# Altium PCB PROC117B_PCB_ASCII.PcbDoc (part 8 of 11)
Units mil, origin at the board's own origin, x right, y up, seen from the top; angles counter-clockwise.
Board outline 2480.32 x 3185.25 mil, 8 copper layers (Top Layer, L2_GND1, L3_SIG1, L4_PWR1, L5_PWR2, L6_SIG2, L7_GND2, Bottom Layer), stack 57.4 mil thick; 456 components, 292 nets, 7831 pads, 2905 vias.
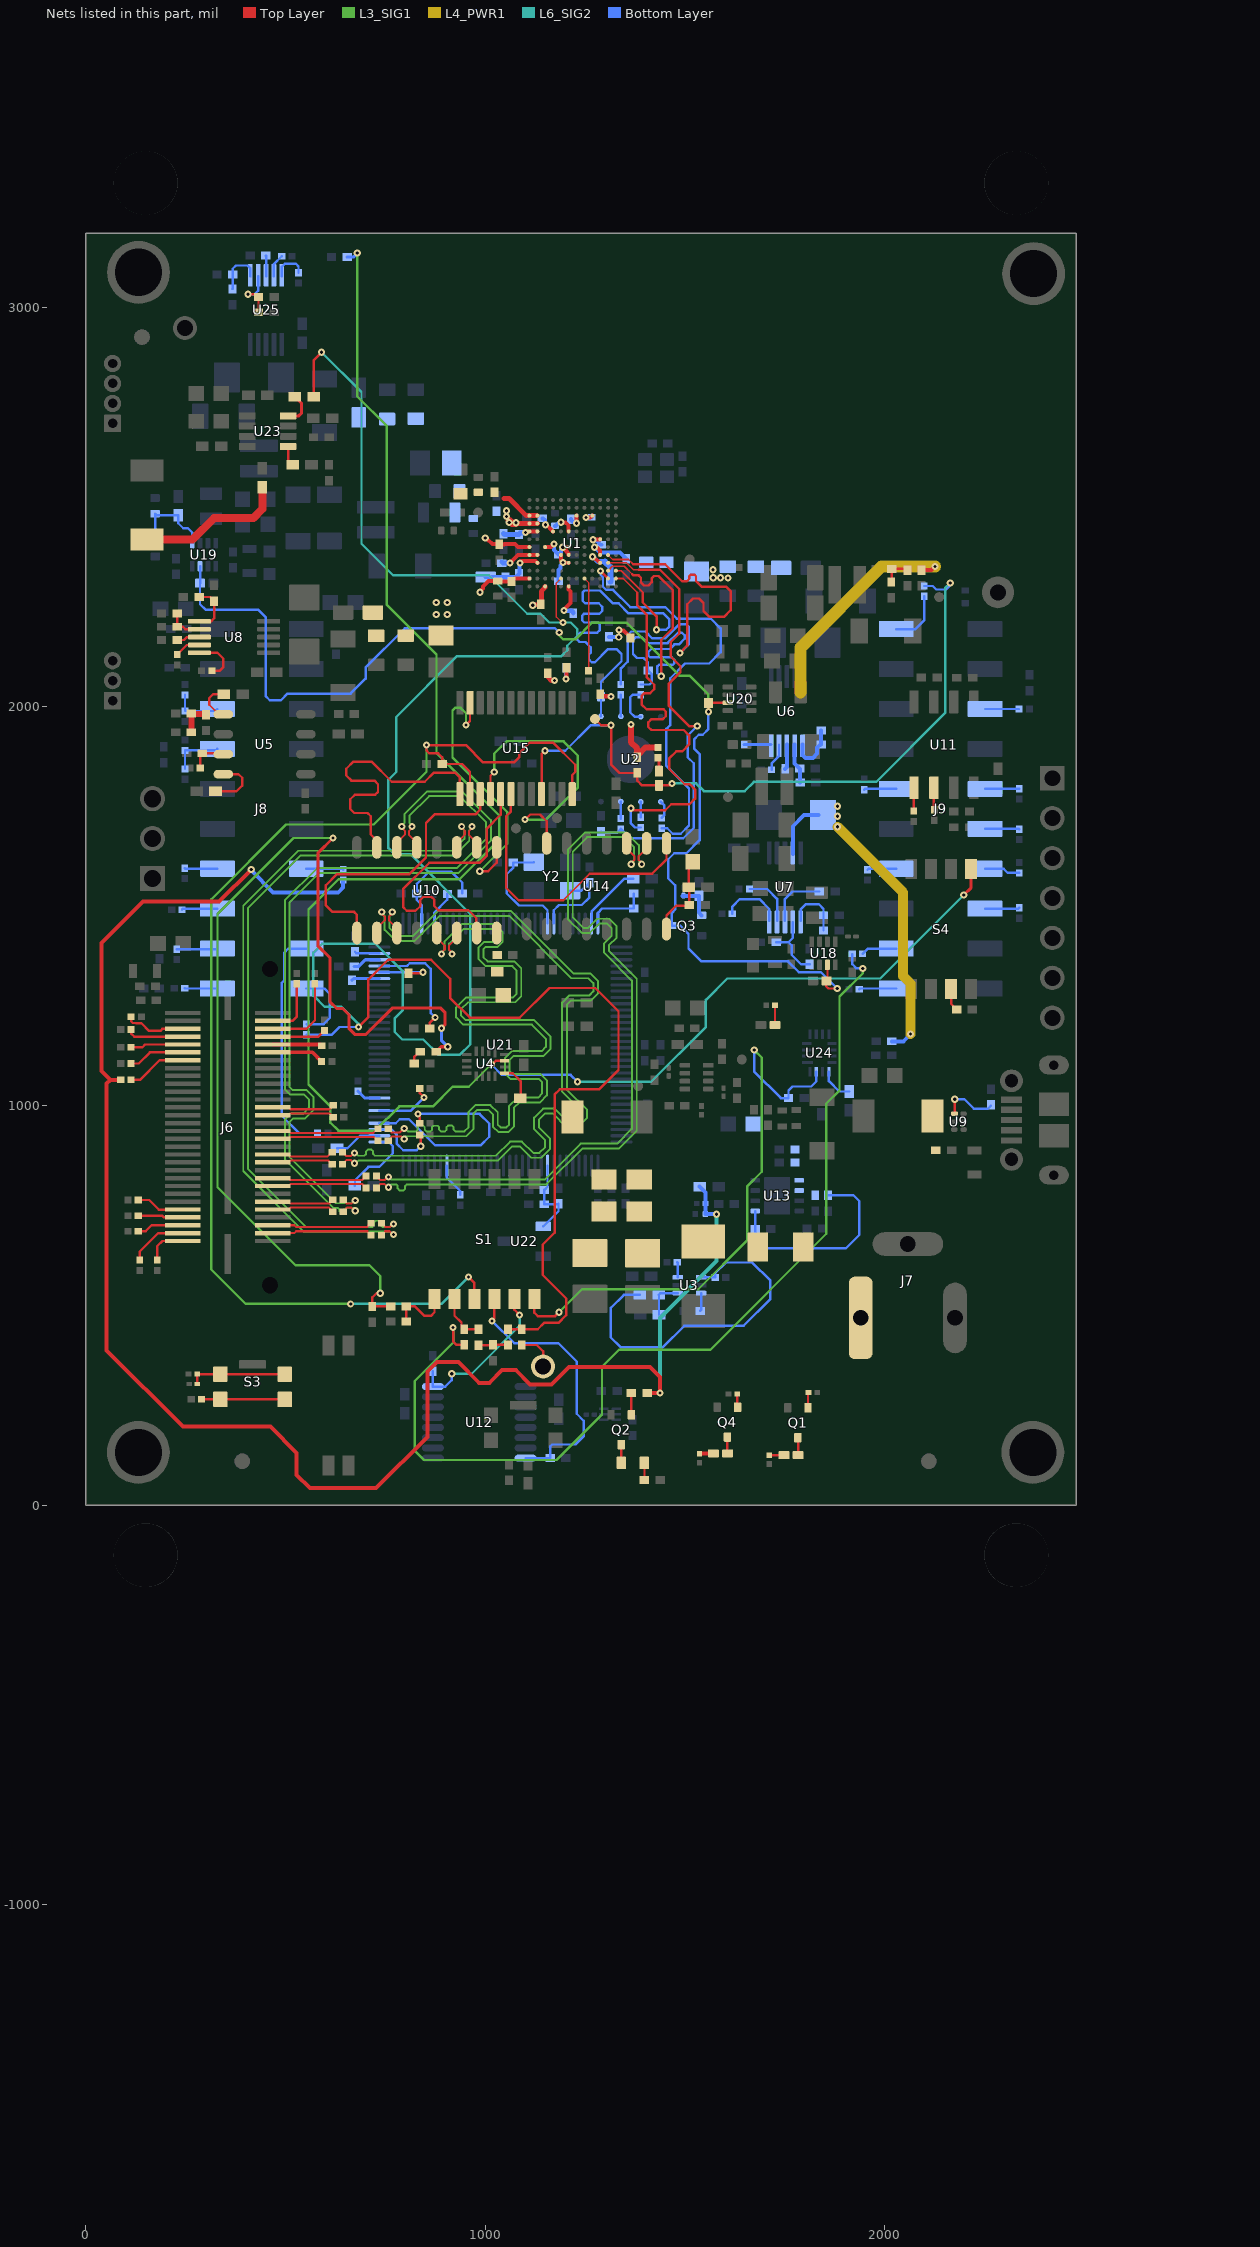
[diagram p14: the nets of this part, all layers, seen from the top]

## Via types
v1: diameter 18, hole 8, Top Layer to Bottom Layer, tented both sides, 2905 vias

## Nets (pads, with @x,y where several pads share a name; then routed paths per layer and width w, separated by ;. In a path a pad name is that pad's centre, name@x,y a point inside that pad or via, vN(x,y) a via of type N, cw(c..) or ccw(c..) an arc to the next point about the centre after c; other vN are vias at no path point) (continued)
MCU_SOP1: R16.1 R155.1 | length 2518.2
  Top Layer w6: v1(919.91,444.7) 919.89,409.86 928.62,401.13 R16.1@947.67,401.13
  L3_SIG1 w6: v1(919.91,444.7) 919.91,406.78 823.3,310.16 823.3,136.89 847.14,113.05 1178.59,113.05 1292.69,227.15 1292.69,346.62 1335.23,389.16 1564.11,389.16 1854.35,679.4 1854.35,1005.5 1887.46,1038.62 1887.46,1273.32 1945.7,1331.56 1945.7,1343.79 v1(1945.49,1344)
  Bottom Layer w6: R155.1@1919.28,1380.28 1919.28,1354.91 1930.18,1344 v1(1945.49,1344)
MODE: Q3.3 R232.2 R238.2 R244.2 U18.3 U19.3 U20.3 | length 3105.4
  Top Layer w6: v1(1559.26,1986.68) 1559.26,2008.42 R244.2@1559.69,2008.85 1607.59,2008.85 U20.3@1608.17,2009.43 ; U18.3@1857.32,1352.93 1857.32,1315.52 R232.2@1854.91,1313.11 1854.46,1312.66 1854.46,1299.03 1859.63,1293.86 v1(1881.7,1293.86)
  L3_SIG1 w6: v1@1185.61,2185.88 1185.61,2177.85 1195.54,2167.91 1226,2167.91 1267.97,2209.88 1353.82,2209.88 1486.51,2077.19 1511.97,2077.19 1559.26,2029.9 v1(1559.26,1986.68)
  Bottom Layer w6: U19.3@286.16,2351.04 R238.2@286.11,2308.62 R238.2@286.11,2308.62 286.11,2256.1 299.66,2242.55 431.64,2242.55 450.31,2223.88 450.31,2025.87 460.62,2015.55 488.66,2015.55 505.32,2032.22 663.1,2032.22 700.58,2069.7 700.58,2097.5 798.99,2195.91 1175.04,2195.91 v1(1185.61,2185.34) ; v1(1559.26,1986.68) 1559.26,1943.26 1545.11,1929.1 1535.12,1929.1 1523.26,1917.24 1523.26,1894.67 1537.18,1880.74 1537.18,1665.42 1504.15,1632.39 1473.5,1632.39 1458.42,1617.31 1458.42,1569.64 1476.23,1551.83 1476.23,1491.76 1467.62,1483.15 Q3.3@1467.62,1451.5 1467.87,1451.26 1488.01,1451.26 1509.34,1429.92 1509.34,1394.29 1541.88,1361.75 1758.66,1361.75 1785.81,1334.6 1840.96,1334.6 v1(1881.7,1293.86)
MUX_CTRL_LVDS_UART_CAN_TP: R90.2 S1.3 U15.14 U15.24 | length 3160.2
  Top Layer w6: v1(958.17,570.96) 973.28,555.85 S1.3@973.28,516.28 ; U15.14@962.27,1780.76 962.27,1835.85 942.3,1855.82 R90.2@892.62,1855.82 892.62,1872.54 882.51,1882.64 860.12,1882.64 853.3,1889.46 v1(853.3,1903.28) 951.71,1903.28 994.95,1860.04 1072.4,1860.04 1085.81,1873.45 1085.81,1883.71 1111.75,1909.66 1170.28,1909.66 1225.91,1854.03 1225.91,1836.12 1218.18,1828.39 U15.24@1218.18,1780.76
  L3_SIG1 w6: v1(663.28,503.85) 400.43,503.85 314.04,590.24 314.04,1516.87 501.67,1704.5 721.23,1704.5 853.3,1836.57 v1(853.3,1903.28)
  L6_SIG2 w6: v1(663.28,503.85) 891.06,503.85 v1(958.17,570.96)
MUX_CTRL_RS232: R7.1 S1.4 U12.16 | length 690.5
  Top Layer w6: v1(1017.54,460.95) 1023.28,466.69 S1.4@1023.28,516.28
  Bottom Layer w6: v1(1017.54,460.95) 1073.22,405.27 1183.59,405.27 1229.28,359.58 1229.28,228.65 1246.56,211.36 1246.56,172.24 1226.19,151.86 1167.93,151.86 1162.84,146.78 R7.1@1162.84,118.04 1162.48,117.68 U12.16@1101.47,117.68
MUX_CTRL_SPI_I2C_MODE: R27.1 S1.6 U24.15 | length 1438.8
  Top Layer w6: S1.6@1123.28,516.28 1123.28,481.84 1131.77,473.35 1175.4,473.35 v1(1185.23,483.18)
  L3_SIG1 w6: v1(1185.23,483.18) 1242.57,540.53 1533.83,540.53 1656.89,663.58 1656.89,799.01 1692.89,835.01 1692.89,1120.7 v1(1673.77,1139.81)
  Bottom Layer w6: v1(1673.77,1139.81) 1673.77,1086.03 1740.65,1019.16 R27.1@1759.66,1019.16 1759.66,1038.02 1770.08,1048.45 1816.75,1048.45 1829.35,1061.05 U24.15@1829.35,1084.99
MUX_CTRL_UARTA_CAN: R8.1 S1.5 U12.8 | length 400.4
  Top Layer w6: S1.5@1073.28,516.28 1073.28,489.46 v1(1086.46,476.28)
  L6_SIG2 w6: v1(916.49,329.15) 966.55,329.15 1086.46,449.06 v1(1086.46,476.28)
  Bottom Layer w6: R8.1@869.18,334.81 U12.8@869.18,296.82 900.12,296.82 916.49,313.19 v1(916.49,329.15)
MUX_CTRL_XDS_DCA_JTAG: R5.1 S4.1 U4.15 | length 4777.2
  Top Layer w6: v1(1015.18,1104.17) 1018.43,1104.17 1027.03,1112.77 1034.08,1112.77 1034.2,1112.89 U4.15@1048.51,1112.89
  Top Layer w8: v1(2198.67,1527.98) 2217.14,1546.45 S4.1@2217.14,1592.74
  L3_SIG1 w6: v1(679.89,3135.52) 679.89,2776.47 754.08,2702.28 754.08,2254.17 878.36,2129.89 878.36,1883.73 1035.67,1726.43 1035.67,1666.68 936.27,1567.28 633.1,1567.28 557.6,1491.79 557.6,1053.57 612.51,998.67 612.51,957.72 632.42,937.81 724.45,937.81 785.3,998.66 869.41,998.66 918.61,1047.85 958.87,1047.85 v1(1015.18,1104.17)
  L6_SIG2 w6: v1(1231.34,1060.32) 1415.38,1060.32 1552.82,1197.76 1552.82,1265.33 1606.41,1318.92 1989.61,1318.92 v1(2198.67,1527.98)
  Bottom Layer w6: v1(1015.18,1104.17) 1041.84,1077.51 1214.15,1077.51 v1(1231.34,1060.32)
  Bottom Layer w8: R5.1@654.68,3125.49 654.92,3125.24 669.61,3125.24 v1(679.89,3135.52)
nERROR_LED_WD_TP: D9.2 R65.2 R100.1 TP2.1 U15.21 | length 1821
  Top Layer w6: U15.21@1141.41,1780.76 1141.41,1881 v1(1149.71,1889.31) ; TP2.1@1274.9,1968.89 1290.75,1953.04 v1(1315.53,1953.04) 1315.53,1854.34 1336.37,1833.5 R65.2@1380.92,1833.5 1380.92,1814.26 1392.76,1802.41 D9.2@1435.28,1802.41 ; D9.2@1435.28,1802.41 1462.5,1802.38 v1@1467.63,1807.51
  L6_SIG2 w6: v1(1467.67,1807.47) 1528.47,1807.47 1547.76,1788.19 1650.09,1788.19 1672.99,1811.1 1979.46,1811.1 2152.06,1983.69 2152.06,2296.46 v1(2164.93,2309.32)
  Bottom Layer w6: v1(1149.71,1889.31) 1200.76,1889.31 1264.13,1952.68 1315.17,1952.68 v1(1315.53,1953.04) ; R100.1@2099.4,2301.73 2121.09,2301.73 2129.82,2293.01 2154.89,2293.01 2164.93,2303.04 v1(2164.93,2309.32)
NET_SOP0: R13.2 R204.2 S1.1 | length 155.5
  Top Layer w6: R13.2@802.59,459.76 802.89,460.06 R204.2@802.89,497.74 824.08,497.74 847.92,473.91 864.36,473.91 873.28,482.83 S1.1@873.28,516.28
NET_SOP1: R16.2 R207.2 S1.2 | length 122.2
  Top Layer w6: S1.2@923.28,516.28 923.4,516.16 923.4,474.42 940.83,456.99 940.83,447.35 R16.2@947.67,440.5 983.35,440.5 R207.2@983.78,440.06
NetC37_2: C37.2 R69.1 U5.3 | length 92.6
  Top Layer w6: R69.1@286.74,1845.83 286.74,1877.52 C37.2@292.16,1882.94 341.9,1882.94 U5.3@344.39,1880.45
NetC39_2: C39.2 R68.1 R79.2 | length 84.7
  Top Layer w15: R68.1@264.25,1982.22 R68.1@264.29,1982.17 ; R79.2@264.29,1935.61 R68.1@264.29,1982.17 ; C39.2@301.17,1979.19 299.66,1980.7 265.76,1980.7 R68.1@264.29,1982.17
NetC42_1: C42.1 C43.1 R9.2 U13.1 U13.2
NetC48_1: C48.1 C63.1 D4.1 F1.1 FB1.1 FB2.1
NetC75_1: C75.1 C88.1 R129.2 U10.16
NetC89_1: C89.1 C90.1 R130.2 U14.16 | length 218.5
  Top Layer w5.98: U14.16@1454.22,1442.61 1454.22,1476.91 1478.67,1501.35 1510.37,1501.35 1511.66,1500.05 C90.1@1511.66,1502.8 1511.66,1545.36 C89.1@1509.64,1547.38 1509.64,1600.73 R130.2@1519.94,1611.02
NetC94_1: C94.1 R169.1 U21.96 | length 158.4
  Bottom Layer w6: U21.96@1282.31,1456.46 1282.31,1483.18 1293.13,1494 C94.1@1372.05,1494 1372.05,1531.25 R169.1@1372.21,1531.41
NetC95_2: C95.2 R202.2 U21.68 | length 268.5
  Bottom Layer w6: U21.68@841.36,1456.46 841.36,1502.91 828.94,1515.32 C95.2@828.94,1531.47 828.94,1555.74 858.91,1585.7 915.72,1585.7 942.55,1558.88 R202.2@942.55,1531.94
NetC97_2: C97.2 U21.89 Y2.3 | length 228.7
  Bottom Layer w6: U21.89@1172.07,1456.46 1172.07,1489.65 1185.32,1502.9 1242.15,1502.9 1261.04,1521.79 C97.2@1261.04,1558.56 1241.36,1538.88 Y2.3@1212.76,1538.88
NetC98_2: C98.2 U21.88 Y2.1 | length 289.1
  Bottom Layer w6: Y2.1@1122.2,1609.74 1121.67,1609.21 C98.2@1070.04,1609.21 1070.04,1595.72 1054.31,1579.99 1054.31,1531.86 1084.49,1501.68 1144.51,1501.68 1156.32,1489.87 U21.88@1156.32,1456.46
NetC99_2: C99.2 C102.2 R233.1 U21.9 U22.1 | length 207
  Bottom Layer w6: U22.1@1145.72,697.96 1183.89,736.13 R233.1@1183.89,754.6 ; U21.9@1156.32,850.16 1156.32,797.41 C102.2@1148.33,789.42 1148.24,789.32 C99.2@1148.24,753.54 R233.1@1182.82,753.54
NetC100_2: C100.2 R119.1 R121.2 U19.5 | length 217.1
  Bottom Layer w6: R119.1@173.4,2482.62 R119.1@174.34,2481.67 ; R121.2@174.34,2415.22 R119.1@174.34,2481.67 ; U19.5@266.47,2409.31 266.47,2435.7 255.95,2446.23 243.87,2446.23 231.43,2458.66 C100.2@231.43,2478.68 177.34,2478.68 R119.1@174.34,2481.67
NetC117_1: C117.1 R10.1 R12.2 U13.5 | length 528.5
  Bottom Layer w6: R12.2@1676.26,691.28 U13.5@1676.26,736.49 ; R12.2@1676.29,691.25 1676.29,657.31 1690.2,643.4 1903.72,643.4 1937.26,676.94 1937.26,761.13 1922.56,775.82 C117.1@1858.8,775.82
NetD1_2: D1.2 L9.2
NetD2_2: D2.2 FB1.2 FB2.2
NetD3_1: D3.1 R172.1 | length 43
  Top Layer w6: D3.1@1398.39,105.75 1399.05,105.09 R172.1@1399.05,62.98
NetD3_2: D3.2 Q2.3 | length 46.1
  Top Layer w6: Q2.3@1340.76,151.61 1341.3,151.08 D3.2@1341.3,105.75
NetD5_1: D5.1 R141.2 | length 37
  Top Layer w6: R141.2@1711.5,125.18 D5.1@1748.53,125.18
NetD5_2: D5.2 Q1.3 | length 44
  Top Layer w6: Q1.3@1783.06,168.8 1783.97,167.89 D5.2@1783.97,125.18
NetD6_1: D6.1 R174.2 | length 49.5
  Top Layer w6: R174.2@1725.81,1251.78 1725.91,1251.68 D6.1@1725.91,1202.37
NetD7_1: D7.1 R28.2 | length 35.3
  Top Layer w10: R28.2@1536.77,128.39 1537.91,129.53 D7.1@1571.65,129.53
NetD7_2: D7.2 Q4.3 | length 41
  Top Layer w6: Q4.3@1606.8,170.39 1606.8,129.81 D7.2@1607.08,129.53
NetD8_1: D8.1 R21.2 | length 374.8
  Top Layer w20: D8.1@153.73,2417.8 267.01,2417.8 321.54,2472.34 419.64,2472.34 442.07,2494.77 R21.2@442.07,2549.34
NetD9_1: D9.1 R64.1 | length 36.6
  Top Layer w6.69: R64.1@1432.93,1871.48 1435.28,1869.12 D9.1@1435.28,1837.84 ; D9.1@1434.35,1832.52 D9.1@1435.77,1831.1
NetF1_2: F1.2 J7.1
NetJ6_4: J6.4 R34.1 | length 146.8
  Top Layer w6: J6.4@468.42,1212.62 517.61,1212.62 528.61,1223.62 R34.1@528.61,1305.63
NetJ6_5: J6.5 R37.2 | length 152.9
  Top Layer w6: R37.2@113.5,1223.18 113.5,1211.62 117.67,1207.46 125.87,1207.46 126.42,1206.91 139.49,1206.91 158.66,1187.74 186.7,1187.74 191.9,1192.94 J6.5@242.83,1192.94
NetJ6_6: J6.6 R38.1 | length 205.8
  Top Layer w6: J6.6@468.42,1192.94 552.46,1192.94 573.87,1214.35 573.87,1305.16 R38.1@573.4,1305.63
NetJ6_7: J6.7 R39.2 | length 142.6
  Top Layer w6: R39.2@113.5,1191.19 113.5,1181.18 121.42,1173.25 J6.7@242.83,1173.25
NetJ6_8: J6.8 R40.1 | length 135.7
  Top Layer w6: J6.8@468.42,1173.25 582.46,1173.25 R40.1@597.77,1188.56
NetJ6_9: J6.9 R41.2 | length 132.3
  Top Layer w6: R41.2@113.5,1146.48 141.6,1146.48 148.69,1153.57 J6.9@242.83,1153.57
NetJ6_10: J6.10 R42.1 | length 124
  Top Layer w9: J6.10@468.42,1153.57 587.3,1153.57 R42.1@590.94,1149.93
NetJ6_11: J6.11 R52.2 | length 140.9
  Top Layer w6: R52.2@113.5,1106.03 132.75,1106.03 160.6,1133.88 J6.11@242.83,1133.88
NetJ6_12: J6.12 R53.1 | length 131.5
  Top Layer w9.42: J6.12@468.42,1133.88 567.36,1133.88 R53.1@590.4,1110.85
NetJ6_13: J6.13 R58.2 | length 149.8
  Top Layer w6: R58.2@113.5,1064.82 135.43,1064.82 184.81,1114.2 J6.13@242.83,1114.2
NetJ6_26: J6.26 R219.1 | length 158.2
  Top Layer w5.2: J6.26@468.42,996.09 507.61,996.09 512.35,991.35 549.22,991.35 ; 549.24,991.32 610.34,991.32 613.39,994.37 613.39,995.55 619.06,1001.22 R219.1@619.85,1001.22
NetJ6_28: J6.28 R220.1 | length 158.2
  Top Layer w5.2: J6.28@468.42,976.4 507.61,976.4 512.35,981.15 544.99,981.15 ; 545.02,981.12 610.34,981.12 613.39,978.08 613.39,976.89 619.06,971.22 R220.1@619.85,971.22
NetJ6_32: J6.32 R221.1 | length 269.4
  Top Layer w5.2: J6.32@468.42,937.03 507.61,937.03 512.35,932.29 720.12,932.29 730.67,942.84 R221.1@731.45,942.84
NetJ6_34: J6.34 R222.1 | length 268.8
  Top Layer w5.2: J6.34@468.42,917.35 507.61,917.35 512.35,922.09 721.41,922.09 730.67,912.84 R222.1@731.45,912.84
NetJ6_38: J6.38 R223.1 | length 155.2
  Top Layer w5.2: J6.38@468.42,877.98 507.61,877.98 512.35,873.24 605.63,873.24 616.39,884 R223.1@617.18,884
NetJ6_40: J6.40 R224.1 | length 154.5
  Top Layer w5.2: J6.40@468.42,858.29 507.61,858.29 512.35,863.04 607.35,863.04 616.39,854 R224.1@617.18,854
NetJ6_44: J6.44 R225.1 | length 240.3
  Top Layer w5.2: J6.44@468.42,818.92 507.61,818.92 512.35,814.18 692.47,814.18 695.52,817.23 695.52,818.41 701.19,824.08 R225.1@701.98,824.08
NetJ6_46: J6.46 R226.1 | length 240.3
  Top Layer w5.2: J6.46@468.42,799.24 507.61,799.24 512.35,803.98 692.47,803.98 695.52,800.93 695.52,799.75 701.19,794.08 R226.1@701.98,794.08
NetJ6_50: J6.50 R227.1 | length 157
  Top Layer w5.2: J6.50@468.42,759.87 507.61,759.87 512.35,755.13 609.13,755.13 612.18,758.17 612.18,759.36 617.84,765.03 R227.1@618.63,765.03
NetJ6_51: J6.51 R59.2 | length 121
  Top Layer w6: R59.2@131.64,763.99 159.01,763.99 182.81,740.18 J6.51@242.83,740.18
NetJ6_52: J6.52 R228.1 | length 157
  Top Layer w5.2: J6.52@468.42,740.18 507.61,740.18 512.35,744.93 609.13,744.93 612.18,741.88 612.18,740.69 617.84,735.03 R228.1@618.63,735.03
NetJ6_53: J6.53 R60.2 | length 113.1
  Top Layer w6: R60.2@131.64,725.13 191.01,725.13 195.64,720.5 J6.53@242.83,720.5
NetJ6_55: J6.55 R61.2 | length 117.3
  Top Layer w6: R61.2@131.64,686.13 149.98,686.13 164.66,700.81 J6.55@242.83,700.81
NetJ6_56: J6.56 R229.1 | length 252.9
  Top Layer w5.2: J6.56@468.42,700.81 521.93,700.81 526.68,696.07 705.01,696.07 708.06,699.12 708.06,700.3 713.72,705.97 R229.1@714.51,705.97
NetJ6_57: J6.57 R62.2 | length 148
  Top Layer w6: R62.2@135.17,613.79 135.17,634.98 181.32,681.13 J6.57@242.83,681.13
NetJ6_58: J6.58 R230.1 | length 252.9
  Top Layer w5.2: J6.58@468.42,681.13 521.93,681.13 526.68,685.87 705.01,685.87 708.06,682.82 708.06,681.64 713.72,675.97 R230.1@714.51,675.97
NetJ6_59: J6.59 R63.2 | length 104.1
  Top Layer w6: R63.2@178.77,613.79 178.77,648.49 191.72,661.44 J6.59@242.83,661.44
NetJ8_5: J8.5 R35.2 R77.2 | length 123.7
  Bottom Layer w6: R35.2@248.36,2028.95 R77.2@248.36,1988.68 324.69,1988.68 J8.5@329.68,1993.67
NetJ8_7: J8.7 R36.2 R118.2 | length 129.1
  Bottom Layer w6: R36.2@248.36,1843.75 R118.2@248.36,1890.03 326.04,1890.03 J8.7@329.68,1893.67
NetJ8_13: J8.13 R146.2 | length 82.6
  Bottom Layer w6: R146.2@247.61,1594.91 248.86,1593.67 J8.13@329.68,1593.67
NetJ8_14: J8.14 R83.1 | length 93.2
  Bottom Layer w6: J8.14@552.12,1593.67 641.84,1593.67 R83.1@644.27,1591.24
NetJ8_15: J8.15 R149.2 | length 89.6
  Bottom Layer w6: R149.2@241,1491.41 243.26,1493.67 J8.15@329.68,1493.67
NetJ8_17: J8.17 R154.2 | length 102.8
  Bottom Layer w6: R154.2@227.56,1392.14 328.15,1392.14 J8.17@329.68,1393.67
NetJ8_18: J8.18 R84.1 | length 578.4
  Bottom Layer w6: J8.18@552.12,1393.67 506.99,1393.67 497.33,1384.01 497.33,1314.65 490.59,1307.91 490.59,974.95 533.72,931.82 R84.1@580.45,931.82
NetJ8_19: J8.19 R163.2 | length 82.4
  Bottom Layer w6: R163.2@247.77,1294.83 248.93,1293.67 J8.19@329.68,1293.67
NetJ8_20: J8.20 R85.1 | length 189.5
  Bottom Layer w6: J8.20@552.12,1293.67 597.36,1293.67 611.02,1280.01 611.02,1219.75 595.46,1204.18 R85.1@552.76,1204.18
NetJ9_1: J9.1 R100.2 | length 139.1
  Bottom Layer w6: J9.1@2029.61,2193.63 2029.75,2193.78 2077.67,2193.78 2099.4,2215.51 R100.2@2099.4,2275.75
NetJ9_6: J9.6 R140.1 | length 85.1
  Bottom Layer w6: J9.6@2252.05,1993.63 2337,1993.63 R140.1@2337.08,1993.71
NetJ9_9: J9.9 R143.2 | length 81
  Bottom Layer w6: R143.2@1949.41,1791.61 1951.43,1793.63 J9.9@2029.61,1793.63
NetJ9_10: J9.10 R144.1 | length 85.8
  Bottom Layer w6: J9.10@2252.05,1793.63 2337.32,1793.63 R144.1@2337.72,1794.03
NetJ9_12: J9.12 R145.1 | length 86
  Bottom Layer w6: J9.12@2252.05,1693.63 2336.91,1693.63 R145.1@2337.72,1692.82
NetJ9_13: J9.13 R147.2 | length 72.9
  Bottom Layer w6: R147.2@1957.66,1591.24 1960.05,1593.63 J9.13@2029.61,1593.63
NetJ9_14: J9.14 R153.1 | length 90
  Bottom Layer w6: J9.14@2252.05,1593.63 2298.41,1593.63 2308.78,1583.26 R153.1@2337.72,1583.26
NetJ9_16: J9.16 R133.1 | length 86.6
  Bottom Layer w6: J9.16@2252.05,1493.63 2335.54,1493.63 R133.1@2337.72,1495.81
NetJ9_17: J9.17 R155.2 | length 89.9
  Bottom Layer w6: R155.2@1945.26,1380.28 1958.61,1393.63 J9.17@2029.61,1393.63
NetJ9_19: J9.19 R164.2 | length 93.3
  Bottom Layer w6: R164.2@1937,1291.98 1938.65,1293.63 J9.19@2029.61,1293.63
NetQ1_1: Q1.1 R171.2 | length 38.8
  Top Layer w6: Q1.1@1808.65,243.61 1808.65,280.53 R171.2@1809.98,281.86
NetQ2_1: Q2.1 R179.2 | length 54.3
  Top Layer w6: R179.2@1366.11,280.58 1366.35,280.34 Q2.1@1366.35,226.41
NetQ3_1: Q3.1 R173.1 R177.2 | length 92.8
  Bottom Layer w10: R173.1@1494.33,1525.59 1535.05,1525.59 R177.2@1535.32,1525.86 1535.32,1484.21 Q3.1@1542.43,1477.09
NetQ4_1: Q4.1 R66.2 | length 33.8
  Top Layer w6: R66.2@1631.45,278.61 1631.45,246.13 Q4.1@1632.39,245.2
NetR2_1: R2.1 R101.2 U6.2 | length 100.5
  Bottom Layer w10: U6.2@1775.29,1904.57 1775.29,1856.87 R2.1@1787.8,1844.36 1788.92,1843.25 R101.2@1788.92,1809.73
NetR6_2: R6.2 U4.13 | length 91.1
  Top Layer w6: U4.13@1048.51,1081.4 1069.31,1081.4 1088.76,1061.95 R6.2@1088.76,1019.14
NetR14_1: R14.1 R103.2 U6.1 | length 132.7
  Bottom Layer w10: U6.1@1794.97,1904.57 1794.97,1878.78 1802.21,1871.55 1820.71,1871.55 1831.38,1882.22 1831.38,1896.8 1839.31,1904.72 R14.1@1841.28,1904.72 R103.2@1841.28,1940.09
NetR18_2: R18.2 U23.1 | length 50.5
  Top Layer w6: U23.1@506.67,2651.02 506.67,2616.45 R18.2@517.96,2605.17
NetR19_2: R19.2 U23.4 | length 85
  Top Layer w8: U23.4@506.67,2727.79 533.6,2727.79 540.25,2734.45 540.25,2759.44 523.95,2775.75 R19.2@523.36,2775.75
NetR25_1: R25.1 U6.5 | length 67.7
  Bottom Layer w8: R25.1@1648.77,1905.1 1649.29,1904.57 U6.5@1716.23,1904.57
NetR29_1: R29.1 U6.4 | length 70.7
  Bottom Layer w6: R29.1@1717.49,1841.58 1717.37,1841.7 1717.37,1857.46 1735.92,1876.01 U6.4@1735.92,1904.57
NetR33_2: R33.2 U24.13 | length 85.3
  Bottom Layer w6: U24.13@1860.85,1084.99 1860.85,1061.77 1886.86,1035.75 R33.2@1912.13,1035.75
NetR45_1: R45.1 U2.5 | length 46.7
  Bottom Layer w6: U2.5@1440.12,1761.12 1448.9,1752.33 1448.9,1728.09 R45.1@1441.84,1721.02
NetR46_2: R46.2 U2.2 | length 53.8
  Bottom Layer w6: U2.2@1340.12,1975.27 R46.2@1340.12,2029.11
NetR47_2: R47.2 U2.3 | length 98.4
  Bottom Layer w6: U2.3@1390.12,1974.49 1374.38,1974.49 1363.19,1985.68 1363.19,2023.11 1369.19,2029.11 R47.2@1390.12,2029.11
NetR48_1: R48.1 U2.6 | length 38.4
  Bottom Layer w6: U2.6@1390.12,1761.12 1390.23,1761 R48.1@1390.23,1722.81
NetR51_1: R51.1 U2.7 | length 42.6
  Bottom Layer w6: R51.1@1340.12,1719.34 U2.7@1340.12,1761.89
NetR54_1: R54.1 U3.3 | length 45.4
  Bottom Layer w6: R54.1@1538.51,486.5 1540.92,488.91 U3.3@1540.92,530.94
NetR55_2: R55.2 U3.6 | length 38.7
  Bottom Layer w6: R55.2@1481.17,608.39 1482.65,606.91 U3.6@1482.65,570.31
NetR56_2: R56.2 R151.1 U3.1 | length 879.9
  Bottom Layer w6: R151.1@1387.68,526.51 1347.5,526.51 1314.79,493.81 1314.79,420.18 1339.34,395.64 1445.56,395.64 1499.12,449.19 1647.29,449.19 1714.24,516.14 1714.24,562.11 1668.72,607.63 1603.11,607.63 1576.37,580.9 R56.2@1576.37,569.98 1576.04,570.31 U3.1@1540.92,570.31
NetR57_1: R57.1 R151.2 U3.4 | length 100
  Bottom Layer w6: R57.1@1435.45,476.26 1435.45,525.98 R151.2@1434.92,526.51 1439.36,530.94 U3.4@1482.65,530.94
NetR67_1: R67.1 R89.2 R131.2 | length 73.9
  Top Layer w6: R131.2@2017.19,2311.78 2018.33,2312.92 R67.1@2018.33,2344.51 2054.84,2344.51 R89.2@2057.77,2341.58
NetR70_1: R70.1 S4.7 | length 57.4
  Top Layer w6: S4.7@2167.14,1292.74 2167.14,1254.86 R70.1@2180.98,1241.02
NetR72_2: R72.2 U9.1 | length 140.1
  Top Layer w6: U9.1@2175.62,979.97 2175.62,1016.05 v1(2175.89,1016.32)
  Bottom Layer w6: v1(2175.89,1016.32) 2200.4,1016.32 2224,992.72 2259.16,992.72 R72.2@2266.65,1000.21
NetR78_2: R78.2 U5.1 | length 102.1
  Top Layer w6: U5.1@344.39,1980.45 333.03,1980.45 309.01,2004.47 309.01,2020.89 318.69,2030.57 R78.2@345.32,2030.57
NetR80_2: R80.2 U5.4 | length 143.3
  Top Layer w6: R80.2@324.73,1787.62 377.38,1787.62 391.67,1801.91 391.67,1821.32 382.54,1830.45 U5.4@344.39,1830.45
NetR93_2: R93.2 U1.E11 | length 235.8
  Top Layer w4: U1.E11@1248.79,2320.4 1259.99,2309.21 1259.99,2090.9 R93.2@1258.82,2089.72
NetR94_2: R94.2 U6.3 | length 62.3
  Bottom Layer w10: R94.2@1751.5,1843.93 1755.6,1848.03 U6.3@1755.6,1904.57
NetR104_1: R104.1 R113.2 U7.2 | length 175.7
  Bottom Layer w6: R104.1@1728.71,1409.73 1759.78,1409.73 ; U7.2@1770.48,1460.19 1770.48,1420.43 1759.78,1409.73 ; R113.2@1812.67,1354.41 1791.37,1354.41 1767.56,1378.22 1767.56,1401.96 1759.78,1409.73
NetR105_1: R105.1 R114.2 U7.1 | length 150.3
  Bottom Layer w6: U7.1@1790.17,1463.14 1790.17,1491.72 1803.56,1505.12 1835.39,1505.12 1847.45,1493.05 R114.2@1847.45,1477.16 R105.1@1847.45,1439.18
NetR106_1: R106.1 R116.2 U8.2 | length 94.4
  Top Layer w6: R116.2@228.88,2232.82 R106.1@228.88,2199.63 243.19,2199.63 249.37,2193.45 U8.2@287.52,2193.45
NetR107_1: R107.1 R117.2 U8.1 | length 122.1
  Top Layer w6: R107.1@283.73,2274.05 311.23,2274.05 R117.2@321.43,2263.84 321.43,2220.76 313.79,2213.12 U8.1@287.54,2213.12
NetR108_1: R108.1 U7.5 | length 157.7
  Bottom Layer w6: R108.1@1619.15,1481.18 1619.15,1499.14 1637.54,1517.52 1686.7,1517.52 1711.42,1492.8 U7.5@1711.42,1463.14
NetR109_1: R109.1 U8.5 | length 116.3
  Top Layer w6: U8.5@287.52,2134.4 329.59,2134.4 344.49,2119.5 344.49,2099.17 334.53,2089.21 316.3,2089.21 R109.1@315.92,2089.59
NetR110_1: R110.1 U7.4 | length 134.4
  Bottom Layer w6: R110.1@1662.02,1542.83 1706.42,1542.83 1731.17,1518.08 1731.17,1463.2 U7.4@1731.11,1463.14
NetR111_1: R111.1 U8.4 | length 68.7
  Top Layer w6: R111.1@228.87,2130.16 228.87,2130.31 252.64,2154.08 U8.4@287.52,2154.08
NetR112_2: R112.2 U7.3 | length 148.6
  Bottom Layer w6: U7.3@1750.79,1463.14 1750.79,1517.61 1769.73,1536.55 R112.2@1837.1,1536.55
NetR115_2: R115.2 U8.3 | length 61.7
  Top Layer w6: R115.2@228.88,2166.36 245.89,2166.36 253.3,2173.77 U8.3@287.52,2173.77
NetR122_1: R122.1 U21.35 | length 175.3
  Top Layer w6: R122.1@836.24,926.97 838.7,924.52 v1(838.7,898.91) v1@836.4,901.21
  Bottom Layer w6: U21.35@735.06,940.71 766.18,940.71 778.34,928.56 778.34,905.31 794.89,888.76 828.54,888.76 v1(838.7,898.91)
NetR124_1: R124.1 U21.36 | length 562
  Top Layer w6: v1(832.04,979.26) 832.04,976.01 836.24,971.8 R124.1@836.24,956.57
  Bottom Layer w6: U21.36@735.06,956.46 776.04,956.46 786.07,966.5 809.45,966.5 875.14,900.8 988.69,900.8 1010.54,922.66 1010.54,955.44 986.09,979.89 832.67,979.89 v1(832.04,979.26)
NetR125_1: R125.1 U21.38 | length 152.8
  Top Layer w6: R125.1@836.24,1043.38 836.24,1031.82 846.95,1021.11 v1(847.21,1021.11)
  Bottom Layer w6: U21.38@735.06,987.96 814.05,987.96 v1(847.21,1021.11)
NetR126_1: R126.1 U21.40 | length 60.4
  Bottom Layer w8: R126.1@681.65,1036.44 698.64,1019.45 U21.40@735.06,1019.45
NetR135_1: R135.1 R148.2 U25.2 | length 131.8
  Top Layer w6: v1@406.39,3032.22 425.95,3032.22 R135.1@432.52,3025.66 R148.2@432.52,2987.41
  Bottom Layer w6: v1(406.36,3032.19) 422.44,3032.19 431.8,3041.56 U25.2@431.8,3076.89
NetR136_1: R136.1 R150.2 U25.1 | length 121.8
  Bottom Layer w6: R150.2@367.15,3045.45 367.87,3046.17 R136.1@367.87,3081.58 367.87,3096.16 375.94,3104.23 404.96,3104.23 412.12,3097.07 412.12,3076.89 U25.1@412.19,3076.96
NetR137_1: R137.1 U25.5 | length 87.5
  Bottom Layer w6: U25.5@490.86,3076.89 490.86,3100.78 498.67,3108.59 526.06,3108.59 532.63,3102.02 R137.1@532.63,3086.13
NetR139_1: R139.1 U25.4 | length 58.6
  Bottom Layer w6: U25.4@471.17,3076.89 471.17,3108.02 R139.1@490.6,3127.45
NetR142_2: R142.2 U25.3 | length 52.2
  Bottom Layer w6: R142.2@451.12,3128.96 451.49,3128.6 U25.3@451.49,3076.89
NetR156_1: R156.1 R203.1 | length 37.2
  Top Layer w6: R156.1@822.24,1105.72 822.24,1121.79 828.96,1128.5 835.8,1135.38 R203.1@837.77,1135.38
NetR159_1: R159.1 U11.6 | length 55.5
  Top Layer w6: U11.6@2123.96,1796.68 2123.96,1741.71 R159.1@2124.33,1741.33
NetR160_1: R160.1 U11.5 | length 59.1
  Top Layer w6: R160.1@2073.05,1737.98 2073.05,1795.77 U11.5@2073.96,1796.68
NetR170_1: R170.1 U21.95 | length 168.2
  Bottom Layer w6: U21.95@1266.56,1456.46 1266.56,1486.9 1348.04,1568.39 1370.13,1568.39 R170.1@1370.47,1568.73
NetR181_2: R181.2 U21.33 | length 192.7
  Bottom Layer w6: R181.2@673.34,800.08 674.03,800.77 674.03,813.44 707.62,847.03 735.04,847.03 769.01,881 769.01,898.89 758.69,909.22 U21.33@735.06,909.22
NetR188_2: R188.2 U21.34 | length 119
  Bottom Layer w6: R188.2@629.1,893.62 655.33,893.62 686.68,924.97 U21.34@735.06,924.97
NetR190_2: R190.2 U21.25 | length 87
  Bottom Layer w6: U21.25@904.35,850.16 904.35,819.78 937.61,786.52 R190.2@937.61,776.98
NetR191_1: R191.1 U21.63 | length 62.6
  Bottom Layer w6: R191.1@674.18,1385.7 678.21,1381.66 U21.63@735.06,1381.66
NetR194_1: R194.1 U21.62 | length 69.9
  Bottom Layer w8: R194.1@672.41,1348.51 682.73,1348.51 700.13,1365.91 U21.62@735.06,1365.91
NetR195_1: R195.1 U21.61 | length 297.4
  Top Layer w6: R195.1@860.93,1193.16 860.93,1206.96 v1(874.88,1220.91)
  Bottom Layer w6: U21.61@735.06,1350.16 804.37,1350.16 811.08,1356.87 849.81,1356.87 863.77,1342.91 863.77,1232.02 v1(874.88,1220.91)
NetR196_1: R196.1 U21.60 | length 146.7
  Top Layer w6: R196.1@808.39,1332.43 842.35,1332.43 v1(844.56,1334.63)
  Bottom Layer w6: U21.60@735.06,1334.41 844.34,1334.41 v1(844.56,1334.63)
NetR203_2: R203.2 R204.1 R205.2 | length 2631.7
  Top Layer w6: R205.2@717.37,497.41 R205.2@717.54,497.58 ; v1(737.37,530.39) 737.27,530.49 727.94,530.49 717.54,520.09 R205.2@717.54,497.58 ; R204.1@763.52,497.74 717.7,497.74 R205.2@717.54,497.58
  Top Layer w7.87: v1(619.04,1670.51) 581.22,1632.69 581.22,1400.98 611.92,1370.29 611.92,1259.76 628.07,1243.61 643.85,1243.61 658.93,1228.53 658.93,1194.18 674.93,1178.18 700.42,1178.18 766.98,1244.74 888.92,1244.74 899.26,1234.4 899.26,1203.08 v1(890.57,1194.39) ; R203.2@877.14,1135.38 889.8,1148.04 v1(906.51,1148.04)
  L3_SIG1 w6: v1(619.04,1670.51) 519.92,1670.51 329.74,1480.33 329.74,796.04 525.22,600.56 710.26,600.56 737.37,573.45 v1(737.37,530.39)
  Bottom Layer w7.87: v1(890.57,1194.39) 890.57,1163.99 v1(906.51,1148.04)
NetR206_2: R206.2 R207.1 R208.2 | length 73.5
  Top Layer w6: R207.1@983.78,400.69 1018.96,400.69 R208.2@1019.54,401.28 1056.67,401.28 R206.2@1056.91,401.03
NetR213_1: R213.1 S3.3 S3.4 | length 208.2
  Top Layer w6: R213.1@289.99,264.9 336.75,264.9 S3.3@336.78,264.86 S3.4@498.2,264.86
NetR214_1: R214.1 R215.1 S3.1 S3.2 | length 243.5
  Top Layer w6: R214.1@279.3,303.27 279.3,327.82 R215.1@279.41,327.93 336.71,327.93 S3.1@336.78,327.85 S3.2@498.2,327.85
NetR231_1: R231.1 U21.70 | length 88.7
  Bottom Layer w6: U21.70@872.86,1456.46 872.86,1483.93 905.32,1516.39 R231.1@905.32,1531.71
NetR234_2: R234.2 U21.59 | length 70.3
  Bottom Layer w8: R234.2@666.49,1314.52 670.64,1318.67 U21.59@735.06,1318.67
PGOOD: R58.1 R83.2 R179.1 R198.1 R201.2 R241.1 | length 4338.4
  Top Layer w10: R58.1@87.52,1064.82 61.67,1064.82 ; v1(414.52,1591.89) 334.16,1511.53 142.75,1511.53 38.97,1407.74 38.97,1087.52 61.67,1064.82 ; R179.1@1405.48,280.58 v1(1437.9,280.58) 1437.9,321.19 1412.99,346.1 1210.24,346.1 1166.27,302.13 1112.95,302.13 1076.75,338.33 1042.47,338.33 1010.57,306.43 985.16,306.43 933.3,358.29 879.17,358.29 855.32,334.44 855.32,170.45 727.31,42.43 561.54,42.43 527.97,76 527.97,130.91 462.5,196.38 243.71,196.38 52.35,387.74 52.35,1055.5 61.67,1064.82
  L6_SIG2 w10: v1(1437.9,280.58) 1437.9,469.12 1579.6,610.82 v1(1579.6,728.52)
  Bottom Layer w10: v1(414.52,1591.89) 414.52,1588.99 469.38,1534.13 632.18,1534.13 644.32,1546.28 644.32,1565.2 R83.2@644.27,1565.25 ; R241.1@1537.34,797.47 1551.7,783.11 R201.2@1551.7,755.51 R198.1@1551.7,728.96 ; R198.1@1551.79,728.87 1551.96,728.7 1579.43,728.7 v1(1579.6,728.52)
PMIC_CLKOUT: R15.2 TP1.1 | length 98
  Top Layer w6: R15.2@1091.59,401.03 1129.46,401.03 1145.25,385.24 TP1.1@1145.25,347.45
PMIC_CLKOUT_LIN_PHY_TX_SOP1: R15.1 R19.1 R85.2 R206.1 U1.H11 | length 5935.2
  Top Layer w4: U1.H11@1189.74,2320.4 1178.49,2309.16 1178.49,2223.95 v1@1195.13,2207.3
  Top Layer w6: R19.1@570.6,2775.75 570.6,2866.75 590.58,2886.73 v1(590.58,2887.2) ; v1(683.02,1197.44) 707.82,1222.24 707.82,1316.5 757.06,1365.73 864.77,1365.73 912.35,1318.15 912.35,1270.21 961.83,1220.73 1086.88,1220.73 1161.28,1295.12 1275.83,1295.12 1334.01,1236.94 1334.01,1089.89 1285.28,1041.16 1186.73,1041.16 1174.15,1028.58 1174.15,682.03 1144.49,652.37 1144.49,576.18 1203.23,517.43 1203.23,475.73 1183.86,456.36 1147.6,456.36 1131.63,440.4 R15.1@1091.59,440.4 R206.1@1056.91,440.4
  L6_SIG2 w6: v1(590.58,2887.2) 690.43,2787.34 690.43,2407.69 769.55,2328.57 1009.09,2328.57 1105.35,2232.32 1138.39,2232.32 1160.51,2210.2 v1(1195.13,2210.2) 1214.63,2210.2 1230.81,2194.02 1230.81,2177.05 1205.85,2152.09 1205.85,2140.78 1191.18,2126.11 929.94,2126.11 777.41,1973.58 777.41,1836.17 757.83,1816.58 757.83,1645.23 772.73,1630.33 812.95,1630.33 962.63,1480.65 962.63,1153.72 937,1128.09 882.92,1128.09 844.99,1166.02 792.58,1166.02 773.25,1185.35 773.25,1218.48 793.46,1238.69 793.46,1337.99 725.72,1405.72 592.17,1405.72 569.84,1383.39 569.84,1276.1 597.86,1248.08 640.33,1248.08 683.18,1205.23 683.18,1197.59 v1(683.02,1197.44)
  Bottom Layer w6: R85.2@552.76,1178.2 616.22,1178.2 635.46,1197.44 v1(683.02,1197.44)
QSPI_CS: R50.2 U1.A10 U2.1 | length 1142.6
  Top Layer w4: U1.A10@1327.8,2339.83 1341,2339.83 1394.57,2286.26 1394.57,2284.49
  Top Layer w6: 1394.75,2284.49 1394.75,2260.36 1429.43,2225.68 v1(1429.43,2192.08)
  Bottom Layer w6: 1280.53,2184.61 1237.87,2184.61 1230.62,2177.36 1230.62,2167.38 1236.51,2161.49 1251.32,2161.49 1264.7,2148.11 1264.7,2134.95 1260.23,2130.48 1260.23,2117.38 1266.95,2110.66 1275.08,2110.66 1308.08,2143.66 1328.89,2143.66 1341.49,2131.06 1341.49,2113.17 1290.12,2061.79 R50.2@1290.12,2024.39 U2.1@1290.12,1975.27 ; 1280.53,2184.72 1287.29,2191.47 1287.29,2205.2 1282.28,2210.2 1248.21,2210.2 1243.14,2215.26 1243.14,2227.64 1247.47,2231.97 1285.81,2231.97 1293.28,2239.44 1293.28,2249.49 1284.46,2258.31 1250.33,2258.31 1244.07,2264.57 1244.07,2285.71 1248.79,2290.43 1287.79,2290.43 1320.21,2258.01 1334.5,2258.01 1359.45,2233.07 1446.42,2233.07 1460.65,2218.84 1460.65,2199.44 1453.29,2192.08 v1(1429.43,2192.08)
QSPI_D0: R45.2 U1.B11 | length 1098.4
  Top Layer w6: v1(1288.92,2339.26) 1288.99,2339.26 U1.B11@1307.85,2320.4
  Bottom Layer w6: v1(1288.92,2339.26) 1288.92,2329.95 1295.15,2323.72 1295.15,2299.99 1303.26,2291.88 1320.44,2291.88 1363.89,2248.43 1451.22,2248.43 1451.35,2248.56 1479.79,2220.12 1565.21,2220.12 1589.78,2195.55 1589.78,2136.12 1561.27,2107.6 1500.73,2107.6 1463.69,2070.57 1463.69,1953.48 1453.94,1943.74 1453.94,1851.12 1510.68,1794.39 1510.68,1702.13 1489.82,1681.28 1469.72,1681.28 1455.96,1695.04 R45.2@1441.84,1695.04
QSPI_D1: R46.1 U1.B8 | length 1084.8
  Top Layer w4: U1.B8@1307.85,2379.46 1319.25,2368.05 1359.18,2368.05 1371.26,2355.97
  Top Layer w6: 1371.26,2355.97 1451.05,2355.97 1493.26,2313.76 1505.56,2313.76 1511.24,2319.43 1511.24,2326.31 1514.75,2329.82 1524.54,2329.82 1528.05,2326.31 1528.05,2314.18 1542.14,2300.09 1603.52,2300.09 1614.86,2288.76 1614.86,2240.79 1598.39,2224.32 1561.78,2224.32 1546.76,2239.34 1546.76,2258.89 1535.2,2270.45 1520.79,2270.45 1506.19,2255.86 1506.19,2152.43 v1(1487.95,2134.18)
  Bottom Layer w6: R46.1@1340.12,2055.09 1340.12,2095.26 1357.31,2112.45 1357.31,2179.11 1365.96,2187.76 1401.23,2187.76 1418.48,2170.5 1450.49,2170.5 1485.66,2205.67 1503.67,2205.67 1510.56,2198.78 1510.56,2156.8 v1(1487.95,2134.18)
QSPI_D2: R44.1 R47.1 U1.B10 | length 1044.8
  Top Layer w4: U1.B10@1307.85,2340.09 1308.28,2340.09 1318.71,2351.36 1348.67,2351.36 1368.05,2331.58
  Top Layer w6: 1368.05,2331.58 1371.28,2328.35 1384.26,2328.35 1390.29,2322.32 1390.29,2310.33 1397.63,2302.98 1408.96,2302.98 1417.05,2311.07 1417.05,2320.9 1422.94,2326.79 1434.41,2326.79 1469.88,2291.33 1469.88,2195.58 1441.21,2166.92 v1(1441.21,2075.59)
  Bottom Layer w6: R47.1@1390.12,2055.09 1411.91,2055.09 1417.13,2060.31 1417.13,2081.35 R44.1@1408.04,2090.43 1407.81,2090.67 1407.81,2110.67 1397.02,2121.46 1380.1,2121.46 1370.25,2131.32 1370.25,2166.4 1377.55,2173.71 1392.44,2173.71 1407.51,2158.63 1456.92,2158.63 1483.1,2184.81 1492.93,2184.81 1499.56,2178.18 1499.56,2169.65 1485.29,2155.38 1474.09,2155.38 1462.66,2143.95 1415.92,2143.95 1409.15,2137.18 1409.15,2126.9 1412.98,2123.08 1467.56,2123.08 1473.6,2117.04 1473.6,2108.07 1470.08,2104.55 1435.33,2104.55 1431.31,2100.52 1431.31,2083.11 1438.83,2075.59 v1(1441.21,2075.59)
QSPI_D3: R49.1 R51.2 U1.B9 | length 1149.6
  Top Layer w4: U1.B9@1307.85,2359.77 1353.84,2359.73 1370.7,2342.88 1384.78,2342.88
  Top Layer w6: 1384.78,2342.88 1437.2,2342.88 1486.06,2294.01 1486.06,2182.26 1464.64,2160.84 1464.64,2125.6 1489.34,2100.9 1489.34,2086.55 1460.31,2057.53 1460.31,2001.32 1510.86,1950.77 v1(1531.18,1950.77)
  Bottom Layer w6: R49.1@1290.46,1686.66 1293.64,1683.48 1330.24,1683.48 R51.2@1340.12,1693.35 1363.61,1669.86 1496.2,1669.86 1522.29,1695.95 1522.29,1857.72 1507.5,1872.51 1507.5,1927.1 v1(1531.18,1950.77)
QSPI_SCLK: R48.2 U1.A11 | length 1103.3
  Top Layer w4: U1.A11@1327.53,2320.4 1345.58,2320.4 1381.45,2284.53
  Top Layer w6: v1(1365.12,1745.05) 1370.12,1740.05 1451.06,1740.05 1466.04,1755.03 1511.57,1755.03 1525.96,1769.42 1525.96,1791.97 1512.76,1805.18 1499.74,1805.18 1460.79,1844.13 1460.79,1869.84 1478.86,1887.91 1493.88,1887.91 1510.75,1904.78 1510.75,1927.51 1497.25,1941.01 1416.65,1941.01 1408.69,1948.97 1408.69,1960.26 1416.7,1968.26 1445.06,1968.26 1452.48,1975.68 1452.48,1987.32 1446.85,1992.94 1404.12,1992.94 1391.86,2005.2 1391.86,2025.85 1399.37,2033.36 1413.37,2033.36 1423.4,2043.39 1423.4,2054.28 1405.06,2072.62 1405.06,2229.48 1381.45,2253.09 1381.45,2284.53
  Bottom Layer w6: v1(1365.12,1745.05) 1365.12,1707.35 1375.64,1696.82 R48.2@1390.23,1696.82
RADAR_1P2_RF: C20.2 C24.2 C44.1 C101.2 C104.2 C111.2 C112.1 R92.2 U1.L4 U1.M4 | length 73.6
  Top Layer w13: v1@1077.19,2459.04 1077.96,2458.27 1130.61,2458.27 U1.L4@1130.68,2458.2
  Top Layer w18: v1@1060.25,2465.85 1067.06,2459.04 v1@1077.19,2459.04
  other v1: 1060.2,2460.76 1077.14,2459.97 1053.21,2475.91 1053.75,2490.24
RADAR_1V2: C25.2 C26.2 C27.2 C28.2 C29.2 C30.1 C45.1 C80.2 C81.2 C110.1 R183.2 U1.C9 U1.G7 U1.G8 U1.G9 U1.H8 U1.K7 U1.L9 U1.M7 | length 607.9
  Top Layer w10: v1(1000.17,2422.1) 1002.33,2422.1 1008.17,2416.26 ; 1008.2,2416.26 1017.96,2406.5 1034.74,2406.5 C26.2@1035.23,2406.02 1047.57,2406.02 1048.09,2406.54 1074.95,2406.54 1082.35,2399.14 U1.M7@1111,2399.14 ; v1(1087.13,2359.05) 1092.41,2364.33 1126.13,2364.33 U1.L9@1130.68,2359.77 ; U1.K7@1150.37,2399.14 1150.44,2399.22 1164.87,2399.22 1172.3,2406.64 v1(1172.38,2406.64) ; U1.H8@1189.74,2379.46 1189.81,2379.39 1189.81,2365.37 v1(1194.76,2360.42) 1209.35,2359.85 U1.G9@1209.42,2359.77 ; v1@1194.58,2399.07 1209.35,2399.07 U1.G7@1209.42,2399.14 ; v1@1194.59,2399.06 1209.35,2381.82 1209.35,2379.53 U1.G8@1209.42,2379.46 ; v1(1268.68,2374.82) 1271.68,2374.82 U1.C9@1287.32,2359.18
  Bottom Layer w10: C27.2@1001.46,2323.8 C30.1@1051.43,2323.8 1076.22,2323.8 C25.2@1084.65,2332.22 1085.89,2333.46 1085.89,2357.81 v1(1087.13,2359.05) ; v1(1172.38,2406.64) 1172.38,2391.47 C29.2@1183.73,2380.12 1185.7,2380.12 1190.54,2384.96 1190.54,2392.87 1194.42,2396.75 v1(1194.42,2398.92) ; C45.1@1183.73,2313.75 1183.73,2341.31 1188.92,2346.5 1188.92,2352.42 1194.76,2358.26 v1(1194.76,2360.42)
  Bottom Layer w12: v1@1270.3,2374.82 1282.36,2362.76 1299.94,2362.76
  Bottom Layer w15: v1(1268.68,2374.82) v1@1270.3,2374.82 ; 1299.94,2362.76 1313.87,2348.83 1313.87,2312.82 C28.2@1313.96,2312.73
  other v1: 877.56,2230.12 905.16,2230.12 877.56,2260.12 905.16,2260.12
RADAR_1V4_APLL: C22.2 U1.G5 | length 56.3
  Top Layer w10: v1(1189.76,2461.14) 1189.8,2461.1 1201.42,2461.1 1209.42,2453.1 U1.G5@1209.42,2438.51
  Bottom Layer w10: C22.2@1174.63,2452.39 1176.6,2452.39 1183.82,2459.61 1188.22,2459.61 v1(1189.76,2461.14)
RADAR_1V4_SYNTH: C18.2 U1.D3 | length 31.8
  Top Layer w10: v1(1252.85,2473.61) 1264.26,2473.61 1268.41,2477.76 1268.41,2477.81 U1.D3@1268.48,2477.88
  Bottom Layer w10: v1(1252.85,2473.61) 1253.03,2473.79 1266.95,2473.79 C18.2@1267.12,2473.96
RADAR_1V8: C4.2 C5.2 C7.2 C8.2 C10.2 C11.2 C12.2 C13.1 C14.2 C15.1 C82.2 C83.2 C109.1 R182.2 U1.C6 U1.C8 U1.F3 U1.J5 U1.K12 U1.L5 U1.L8 U1.M5 U1.M8 | length 497.9
  Top Layer w10: v1(1062.41,2359.66) 1062.41,2359.78 1082.08,2379.46 U1.M8@1111,2379.46 U1.L8@1130.68,2379.46 ; v1(1101.21,2435.53) 1104,2438.32 1130.49,2438.32 U1.L5@1130.68,2438.51 ; v1(1151.01,2455.11) 1153.17,2455.11 1168.85,2439.44 1169.13,2439.44 U1.J5@1170.05,2438.51 ; v1(1229.11,2458.94) U1.F3@1229.11,2477.88 ; v1(1270.5,2417.74) 1271.52,2418.76 1288.09,2418.76 U1.C6@1288.16,2418.83 ; v1@1281.61,2396.99 1288.16,2390.45 U1.C8@1288.16,2379.46
  Top Layer w12: v1(1119.17,2253.33) 1120.71,2254.86 1137.82,2254.86 C7.2@1139.43,2256.48 1141.12,2258.17 1141.12,2288.45 1149.73,2297.06 U1.K12@1149.73,2300.72
  Bottom Layer w10: C4.2@1143.1,2471.28 1144.64,2471.28 1149.48,2466.44 1149.48,2456.64 v1(1151.01,2455.11) ; C5.2@1215,2469.3 1215,2467.34 1219.84,2462.49 1221.81,2462.49 1223.82,2460.48 1227.58,2460.48 v1(1229.11,2458.94) ; v1(1270.5,2417.74) 1272.03,2416.21 1278.29,2416.21 1289.49,2405.01 C14.2@1291.46,2405.01 ; v1(1273.96,2398.53) 1287.31,2385.18 1338.1,2385.18 C10.2@1352.6,2370.69
  Bottom Layer w12: C8.2@1041.52,2362.67 1045.03,2359.17 1061.91,2359.17 v1(1062.41,2359.66)
  Bottom Layer w13: C12.2@1046.09,2432.96 1048.45,2430.59 C11.2@1084.79,2430.59 1084.79,2431.23 1088.13,2434.57 1100.25,2434.57 v1(1101.21,2435.53)
  other v1: 1571.22,2322.56 1589.53,2322.56 1608.48,2321.93 1570.9,2342.31
RADAR_1V_RF_OUT: C9.2 C19.2 C23.1 U1.L3 U1.M3 | length 101.1
  Top Layer w12: 1047.39,2520.95 1059.82,2520.95 1102.81,2477.96 1110.93,2477.96 U1.M3@1111,2477.88 U1.L3@1130.68,2477.88
RADAR_3V3: C16.2 C17.2 C21.2 R4.2 R20.2 R23.1 R64.2 R65.1 R73.2 R74.2 R75.2 R81.2 R82.2 R200.2 U1.G12 U1.M11 U7.9 | length 1928.6
  Top Layer w10: v1(987.14,2286) 987.14,2288.16 994.3,2295.32 994.3,2300.33 1007.96,2314 C17.2@1031.69,2314 1032.71,2312.97 C21.2@1066.08,2312.97 1073.51,2320.4 U1.M11@1111,2320.4 ; v1(1197.74,2240.72) 1197.74,2242.83 1213.67,2258.76 1213.67,2288.36 1209.42,2292.61 U1.G12@1209.42,2300.72 ; v1(1202.32,2069.12) 1203.27,2070.07 1203.27,2096.31 R82.2@1203.42,2096.46 ; v1(1335,2191.88) 1336.53,2190.35 1346.91,2190.35 1363.83,2173.44 R73.2@1363.83,2171.47 ; R20.2@2092.59,2341.64 2117.7,2341.64 v1(2126.92,2350.87)
  Top Layer w12: R74.2@1156.68,2083.28 1156.68,2074.57 1166.27,2064.98 v1(1173.79,2064.98) ; R4.2@1288.24,2030.82 1288.24,2029.7 1292.09,2025.86 1313.89,2025.86 v1(1315.04,2024.71)
  Top Layer w15: v1(1365.16,1954.67) 1365.16,1910.82 1380.92,1895.06 1380.92,1876.81 1401.57,1897.46 R64.2@1432.93,1897.46
  L4_PWR1 w25: v1(1882.37,1698.75) 2046.47,1534.65 2046.47,1325.08 2065.22,1306.32 v1(2065.22,1179.59)
  L4_PWR1 w30: 1790.12,2035.59 1790.12,2147.81 1993.18,2350.87 v1(2126.92,2350.87)
  Bottom Layer w10: v1(1202.32,2069.12) 1202.87,2069.67 1202.87,2095.91 R81.2@1203.42,2096.46 ; R75.2@1310.15,2174.2 1310.45,2173.9 1334.37,2173.9 v1(1334.67,2173.6) ; U7.9@1770.48,1630.46 1770.48,1700.07 1798.75,1728.34 R200.2@1835.38,1728.34 ; R23.1@2018.64,1161.23 2018.72,1161.23 2047.11,1161.23 2065.22,1179.34 v1(2065.22,1179.59)
  Bottom Layer w12: v1(1197.74,2240.72) 1198.89,2239.58 1216.75,2239.58 1220.59,2235.73 C16.2@1220.59,2233.82
  other v1: 1882.74,1725.2 1882.74,1750.15
RADAR_LVDS_0M: R230.2 U10.3 | length 1865.2
  Top Layer w5.2: R230.2@740.5,675.97 741.28,675.97 746.95,681.64 746.95,682.82 750,685.87 761.05,685.87 768.95,677.97 v1(770.5,677.97) ; U10.3@929.03,1647.18 929.03,1659.07 948.93,1678.97 948.93,1688.42 941.25,1696.1 v1(941.25,1699.56)
  L3_SIG1 w4.8: v1(770.5,677.97) 768.03,677.97 761.03,684.97 546.03,684.97 394.27,836.73 394.27,1500.36 532.64,1638.73 918.65,1638.73 948.25,1668.33 948.25,1690.09 941.25,1697.09 v1(941.25,1699.56)
RADAR_LVDS_0P: R229.2 U10.2 | length 1866.5
  Top Layer w5.2: R229.2@740.5,705.97 741.28,705.97 746.95,700.3 746.95,699.12 750,696.07 761.05,696.07 768.95,703.97 v1(770.5,703.97) ; v1(967.25,1699.56) 967.25,1696.1 959.13,1687.98 959.13,1678.97 979.03,1659.07 U10.2@979.03,1647.18
  L3_SIG1 w4.8: v1(770.5,703.97) 768.03,703.97 761.03,696.97 742.71,696.97 739.79,699.89 739.79,707.75 735.3,712.24 726.58,712.24 721.46,707.13 721.46,700.61 717.82,696.97 551,696.97 406.27,841.7 406.27,1495.39 537.61,1626.73 923.62,1626.73 960.25,1663.36 960.25,1690.09 967.25,1697.09 v1(967.25,1699.56)
RADAR_LVDS_1M: R228.2 U10.5 | length 1963.7
  Top Layer w5.2: R228.2@644.61,735.03 645.4,735.03 651.07,740.69 651.07,741.88 654.12,744.93 665.17,744.93 673.07,737.03 v1(674.61,737.03) ; v1(817.25,1699.56) 817.25,1696.1 809.13,1687.98 809.13,1678.97 829.03,1659.07 U10.5@829.03,1647.18
  L3_SIG1 w4.8: v1(674.61,737.03) 674.61,740.47 671.06,744.03 650.94,744.03 647.09,740.17 647.09,734.88 644,731.79 638.26,731.79 634.73,735.32 634.73,741.16 631.86,744.03 621.32,744.03 498.57,866.77 498.57,964.53 514.43,980.39 544.14,980.39 558.52,994.77 558.52,1016.16 546.81,1027.87 512.31,1027.87 498.57,1041.61 498.57,1514.49 579.14,1595.05 928.65,1595.05 1002.28,1668.68 1002.28,1710.36 937.06,1775.58 859.86,1775.58 810.25,1725.97 810.25,1709.03 817.25,1702.03 v1(817.25,1699.56)
RADAR_LVDS_1P: R227.2 U10.6 | length 1964.7
  Top Layer w5.2: R227.2@644.61,765.03 645.4,765.03 651.07,759.36 651.07,758.17 654.12,755.13 665.17,755.13 673.07,763.03 v1(674.61,763.03) ; U10.6@779.03,1647.18 779.03,1659.07 798.93,1678.97 798.93,1688.42 791.25,1696.1 v1(791.25,1699.56)
  L3_SIG1 w4.8: v1(674.61,763.03) 672.14,763.03 665.14,756.03 626.29,756.03 510.57,871.74 510.57,959.56 519.4,968.39 549.11,968.39 570.52,989.8 570.52,1021.13 551.78,1039.87 517.28,1039.87 510.57,1046.58 510.57,1509.52 584.11,1583.05 933.62,1583.05 1014.28,1663.71 1014.28,1715.34 942.03,1787.58 854.89,1787.58 798.25,1730.94 798.25,1709.03 791.25,1702.03 v1(791.25,1699.56)
RADAR_LVDS_2M: R224.2 U10.11 | length 1964.6
  Top Layer w5.2: R224.2@643.16,854 643.95,854 649.62,859.66 649.62,860.85 652.66,863.9 663.72,863.9 671.62,856 v1(673.16,856) ; v1(767.25,1485) 767.25,1481.53 759.13,1473.41 759.13,1464.41 779.03,1444.51 U10.11@779.03,1432.62
  L3_SIG1 w4.8: v1(673.16,856) 675.63,856 682.63,863 1031.99,863 1067.58,898.59 1087.32,898.59 1115.98,869.94 1141.07,869.94 1162.45,891.31 1162.45,918.63 1134.68,946.4 1134.68,965.3 1150.26,980.89 1169.07,980.89 1204.97,944.99 1230.33,944.99 1255.17,969.82 1255.17,989.95 1204.69,1040.43 1204.69,1253.53 1215.37,1264.22 1265.55,1264.22 1283.08,1281.74 1283.08,1312.04 1263.61,1331.51 1221.27,1331.51 1065.34,1487.43 881.2,1487.43 818.6,1424.84 781.07,1424.84 760.25,1445.66 760.25,1475.53 767.25,1482.53 v1(767.25,1485)
RADAR_LVDS_2P: R223.2 U10.10 | length 1964.8
  Top Layer w5.2: R223.2@643.16,884 643.95,884 649.62,878.33 649.62,877.14 652.66,874.1 663.72,874.1 671.62,882 v1(673.16,882) ; U10.10@729.03,1432.62 729.03,1444.51 748.93,1464.41 748.93,1473.85 741.25,1481.53 v1(741.25,1485)
  L3_SIG1 w4.8: v1(673.16,882) 675.63,882 682.63,875 697.63,875 701.18,878.55 701.18,885.15 706.3,890.27 715.02,890.27 719.51,885.78 719.51,879.32 723.83,875 1027.02,875 1062.61,910.59 1092.29,910.59 1120.95,881.94 1136.1,881.94 1150.45,896.28 1150.45,913.66 1122.68,941.43 1122.68,970.27 1145.29,992.89 1174.04,992.89 1209.94,956.99 1225.36,956.99 1243.17,974.79 1243.17,984.98 1192.69,1035.46 1192.69,1258.51 1210.4,1276.22 1260.58,1276.22 1271.08,1286.71 1271.08,1307.07 1258.64,1319.51 1216.3,1319.51 1060.37,1475.43 886.17,1475.43 823.57,1412.84 776.1,1412.84 748.25,1440.69 748.25,1475.53 741.25,1482.53 v1(741.25,1485)
RADAR_LVDS_3M: R222.2 U10.13 | length 1851.3
  Top Layer w5.2: R222.2@757.44,912.84 758.22,912.84 763.89,918.51 763.89,919.69 766.94,922.74 789.91,922.74 ; 789.91,922.82 795.89,916.84 v1(797.44,916.84) ; U10.13@879.03,1432.62 879.03,1420.72 898.93,1400.82 898.93,1391.82 890.81,1383.7 v1(890.81,1380.24)
  L3_SIG1 w4.8: v1(797.44,916.84) 797.44,919.6 801.68,923.84 952.82,923.84 970.42,941.44 970.42,979.84 980.27,989.69 1008.47,989.69 1019.73,978.43 1019.73,948.12 1033.81,934.04 1058.28,934.04 1072.26,948.02 1072.26,994.72 1086.22,1008.68 1137.67,1008.68 1154.88,1025.89 1154.88,1063.53 1138.87,1079.53 1068.03,1079.53 1061.39,1086.17 1061.39,1114.71 1071.75,1125.07 1146.57,1125.07 1164.24,1142.75 1164.24,1172.74 1121.87,1215.1 950.64,1215.1 939.34,1226.4 939.34,1241.37 957.31,1259.34 1074.99,1259.34 1090.56,1274.91 1090.56,1344.27 1073.14,1361.69 1006.19,1361.69 995.65,1372.22 995.65,1391.7 1001.91,1397.96 1031.25,1397.96 1043.12,1409.82 1043.12,1435.67 1023.64,1455.15 942.06,1455.15 897.81,1410.9 897.81,1389.71 890.81,1382.71 v1(890.81,1380.24)
RADAR_LVDS_3P: R221.2 U10.14 | length 1850.2
  Top Layer w5.2: R221.2@757.44,942.84 758.22,942.84 763.89,937.17 763.89,935.99 766.94,932.94 786.07,932.94 ; 786.07,933.02 795.89,942.84 v1(797.44,942.84) ; v1(916.81,1380.24) 916.81,1383.7 909.13,1391.38 909.13,1400.82 929.03,1420.72 U10.14@929.03,1432.62
  L3_SIG1 w4.8: v1(797.44,942.84) 799.91,942.84 806.91,935.84 826.91,935.84 830.46,939.39 830.46,945.99 834.52,950.06 845.34,950.06 848.78,946.62 848.78,940.17 853.11,935.84 863.11,935.84 866.66,939.39 866.66,945.99 870.74,950.07 881.53,950.07 884.99,946.62 884.99,940.17 889.31,935.84 899.31,935.84 902.86,939.39 902.86,945.99 907.48,950.61 917.2,950.61 921.19,946.62 921.19,940.17 925.52,935.84 947.85,935.84 958.42,946.41 958.42,984.81 975.3,1001.69 1013.44,1001.69 1031.73,983.4 1031.73,953.09 1038.78,946.04 1053.31,946.04 1060.26,952.99 1060.26,999.69 1081.25,1020.68 1132.7,1020.68 1142.88,1030.86 1142.88,1058.56 1133.9,1067.53 1063.06,1067.53 1049.39,1081.2 1049.39,1119.68 1066.78,1137.07 1141.6,1137.07 1152.24,1147.72 1152.24,1167.77 1116.9,1203.1 945.67,1203.1 927.34,1221.43 927.34,1246.34 952.34,1271.34 1070.02,1271.34 1078.56,1279.88 1078.56,1339.3 1068.17,1349.69 1001.21,1349.69 983.65,1367.25 983.65,1396.67 996.94,1409.96 1026.28,1409.96 1031.12,1414.79 1031.12,1430.7 1018.67,1443.15 947.03,1443.15 909.81,1405.93 909.81,1389.71 916.81,1382.71 v1(916.81,1380.24)
RADAR_LVDS_CLK: U14.1 U15.18 | length 736.9
  Top Layer w6: U15.18@1064.64,1780.76 1064.52,1780.65 1064.52,1737.25 1052.78,1725.51 1052.78,1545.51 1083.68,1514.62 1195.71,1514.62 1262.05,1580.96 1418.08,1580.96 1454.22,1617.11 U14.1@1454.22,1657.18
RADAR_LVDS_CLKM: R226.2 U14.3 | length 1879.5
  Top Layer w5.2: R226.2@727.96,794.08 728.75,794.08 734.41,799.75 734.41,800.94 737.46,803.98 748.51,803.98 756.41,796.08 v1(757.96,796.08) ; U14.3@1354.22,1657.18 1354.22,1645.29 1374.12,1625.39 1374.12,1616.38 1366.01,1608.26 v1(1366.01,1604.8)
  L3_SIG1 w4.8: v1(757.96,796.08) 764.94,803.1 777.53,803.1 781.09,799.55 781.09,792.94 786.2,787.82 794.92,787.82 799.41,792.32 799.41,798.77 803.74,803.1 1153.69,803.1 1243.98,893.38 1335.63,893.38 1379.64,937.4 1379.64,1318.61 1309.82,1388.44 1309.82,1402.04 1329.02,1421.24 1329.02,1450.18 1310.78,1468.42 1281.03,1468.42 1257.4,1444.79 1247.38,1444.79 1219.41,1472.75 1219.41,1636.65 1255.62,1672.85 1347.94,1672.85 1373.01,1647.78 1373.01,1614.27 1366.01,1607.27 v1(1366.01,1604.8)
RADAR_LVDS_CLKP: R225.2 U14.2 | length 1879
  Top Layer w5.2: R225.2@727.96,824.08 728.75,824.08 734.41,818.41 734.41,817.23 737.46,814.18 748.51,814.18 756.41,822.08 v1(757.96,822.08) ; v1(1392.01,1604.8) 1392.01,1608.26 1384.32,1615.95 1384.32,1625.39 1404.22,1645.29 U14.2@1404.22,1657.18
  L3_SIG1 w4.8: v1(757.96,822.08) 757.96,821.91 764.78,815.1 1148.72,815.1 1239.01,905.38 1330.66,905.38 1367.64,942.37 1367.64,1313.64 1297.82,1383.47 1297.82,1407.01 1317.02,1426.21 1317.02,1445.21 1305.81,1456.42 1286,1456.42 1262.37,1432.79 1242.41,1432.79 1207.41,1467.78 1207.41,1641.62 1250.65,1684.85 1352.91,1684.85 1385.01,1652.75 1385.01,1614.27 1392.01,1607.27 v1(1392.01,1604.8)
RADAR_LVDS_DATA0: U10.1 U15.11 | length 708.7
  Top Layer w6: v1(952.08,1953.58) 962.27,1963.77 U15.11@962.27,2009.1 ; v1(986.56,1587.41) 1007.56,1587.41 1029.03,1608.88 U10.1@1029.03,1647.18
  L3_SIG1 w6: v1(952.08,1953.58) 952.08,1982.9 938.49,1996.49 924.56,1996.49 918.33,1990.26 918.33,1872.4 1055.28,1735.45 1055.28,1656.12 v1(986.56,1587.41)
RADAR_LVDS_DATA1: U10.7 U15.13 | length 737.8
  Top Layer w6: U10.7@729.03,1647.18 729.03,1663.92 713.64,1679.31 713.64,1724.91 705.38,1733.17 672.4,1733.17 662.33,1743.24 662.33,1767.49 673.8,1778.96 724.41,1778.96 731.68,1786.24 731.68,1805.38 722.82,1814.24 665.26,1814.24 652.15,1827.35 652.15,1843.86 670.29,1862 715.42,1862 766.08,1811.35 848.77,1811.35 871.72,1834.3 924.87,1834.3 936.68,1822.49 U15.13@936.68,1780.76
RADAR_LVDS_DATA2: U10.9 U15.15 | length 738.6
  Top Layer w6: U10.9@679.03,1432.62 679.03,1478.5 671.94,1485.59 617.43,1485.59 601.28,1501.75 601.28,1552.5 628.93,1580.15 810.3,1580.15 851.87,1621.73 851.87,1708.15 873.5,1729.77 975.75,1729.77 987.86,1741.89 U15.15@987.86,1780.76
RADAR_LVDS_DATA3: U10.15 U15.17 | length 737.5
  Top Layer w6: U10.15@979.03,1432.62 977.73,1433.91 977.73,1470.16 958.07,1489.83 882.92,1489.83 872.45,1500.3 872.45,1516.32 865.96,1522.81 845.17,1522.81 837.38,1515.02 837.38,1499.86 825.77,1488.26 803.86,1488.26 794.64,1497.48 794.64,1542.93 859.98,1608.27 985.64,1608.27 1004.54,1627.17 1004.54,1694.44 1038.83,1728.73 1038.83,1770.51 1039.05,1770.72 U15.17@1039.05,1780.76
RADAR_LVDS_FRCLK: U14.7 U15.16 | length 709.4
  Top Layer w6: U15.16@1013.46,1780.76 1013.46,1826.43 v1(1022.99,1835.97) ; v1(1100.08,1716.78) 1112.89,1729.59 1137.35,1729.59 1154.22,1712.72 U14.7@1154.22,1657.18
  L3_SIG1 w6: v1(1022.99,1835.97) 1022.99,1881.82 1053.79,1912.62 1196.45,1912.62 1232.45,1876.62 1232.45,1796.91 1152.32,1716.78 v1(1100.08,1716.78)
